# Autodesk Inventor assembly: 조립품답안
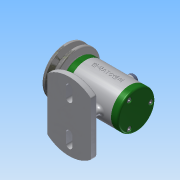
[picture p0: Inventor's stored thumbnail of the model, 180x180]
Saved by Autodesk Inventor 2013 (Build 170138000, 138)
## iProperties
Created: 2017-12
Part Number: 조립품답안
Document SubType Name: Assembly
Designer: Administrator
Author: Administrator
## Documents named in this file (14)
- C:\Users\Administrator\Desktop\471208V1013\답안조립품.iam
- C:\Users\Administrator\Desktop\471208V1013\본체.ipt
- C:\Users\Administrator\Desktop\471208V1013\V벨트풀리.ipt
- C:\Users\Administrator\Desktop\471208V1013\고무캡.ipt
- C:\Users\Administrator\Desktop\471208V1013\너트 M 8.ipt
- C:\Users\Administrator\Desktop\471208V1013\뒤커버.ipt
- C:\Users\Administrator\Desktop\471208V1013\베어링 15 x 32 x 9.ipt
- C:\Users\Administrator\Desktop\471208V1013\볼트 M4 x 12.ipt
- C:\Users\Administrator\Desktop\471208V1013\스프링와셔 8.ipt
- C:\Users\Administrator\Desktop\471208V1013\앞커버.ipt
- C:\Users\Administrator\Desktop\471208V1013\오일 실 15 25 7.ipt
- C:\Users\Administrator\Desktop\471208V1013\와셔 8x17.ipt
- C:\Users\Administrator\Desktop\471208V1013\축.ipt
- C:\Users\Administrator\Desktop\471208V1013\키 3 x 3 x 12.ipt
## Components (2 placed, 2 different names)
1. V벨트풀리:1 — 각도:2
2. 고무캡:1
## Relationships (1: Angle 1)
- 각도:2 [Angle]: V벨트풀리:1
